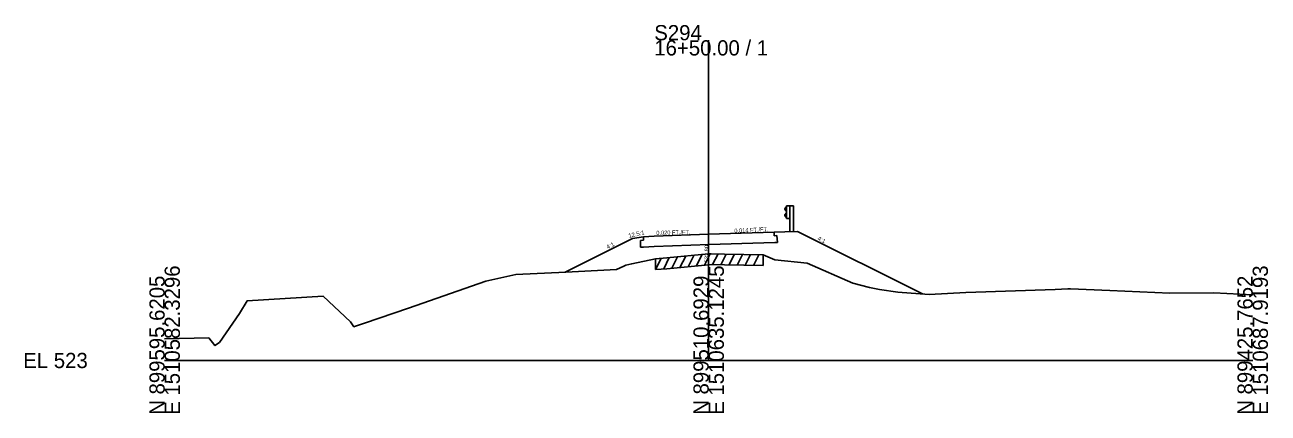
# Model space of a CAD drawing. Extents: x 974 to 2203, y -10 to 19041.
# Drawn here: x 974.3 to 1202.8, y 12990.3 to 13061.7 of the extents above; entities that cross this region are included whole.
import ezdxf

# ---------------------------------------------------------------- set-up
doc = ezdxf.new("R2010")
doc.units = 0
for name, color, linetype in [('RD_GPK_XS_Cell', 7, 'Continuous'), ('RD_XS_Base', 7, 'Continuous'), ('RD_XS_EarthShd', 7, 'Continuous'), ('RD_XS_ExGround', 7, 'Continuous'), ('RD_XS_ExPaveRet', 7, 'Continuous'), ('RD_XS_GR', 7, 'Continuous'), ('RD_XS_Pave', 7, 'Continuous'), ('RD_XS_TX_Elev_EX', 7, 'Continuous'), ('RD_XS_TX_Slope', 7, 'Continuous')]:
    doc.layers.add(name, color=color, linetype=linetype)

msp = doc.modelspace()

# ---------------------------------------------------------------- linework, layer by layer
at = {"layer": 'RD_GPK_XS_Cell'}
for p, q in [((1100, 13000), (1100, 13058.91)), ((1000, 13000), (1100, 13000)), ((1100, 13000), (1200, 13000))]:
    msp.add_line(p, q, dxfattribs=at)
at = {"layer": 'RD_XS_Base'}
for p, q in [((1088, 13022.12), (1087.5, 13022.1)), ((1087.5, 13020.83), (1087.5, 13022.1)), ((1088, 13022.12), (1088, 13022.76)), ((1112.05, 13022.96), (1112.01, 13023.59)), ((1112.05, 13022.96), (1112.55, 13022.97)), ((1112.64, 13021.7), (1112.55, 13022.97)), ((1088, 13020.85), (1087.5, 13020.83)), ((1088, 13020.85), (1090, 13020.94)), ((1090, 13020.94), (1100.07, 13021.36)), ((1110.14, 13021.63), (1100.07, 13021.36)), ((1112.14, 13021.69), (1110.14, 13021.63)), ((1112.14, 13021.69), (1112.64, 13021.7))]:
    msp.add_line(p, q, dxfattribs=at)
at = {"layer": 'RD_XS_EarthShd'}
for p, q in [((1086, 13022.43), (1073.61, 13016.23)), ((1088, 13022.76), (1086, 13022.43)), ((1112.01, 13023.59), (1114, 13023.65)), ((1114, 13023.65), (1116.32, 13023.71)), ((1116.32, 13023.71), (1139.29, 13012.23))]:
    msp.add_line(p, q, dxfattribs=at)
at = {"layer": 'RD_XS_ExGround'}
msp.add_lwpolyline([(1000, 13003.96), (1008.12, 13004.17), (1009.24, 13002.73), (1010.07, 13003.3), (1013.73, 13008.67), (1015.2, 13010.98), (1029.15, 13011.83), (1034.15, 13007.09), (1034.79, 13006.21), (1035.1, 13006.31), (1036.74, 13006.89), (1044.84, 13009.6), (1059.07, 13014.62), (1064.53, 13015.8), (1073.72, 13016.24), (1083.05, 13016.71), (1084.42, 13017.34), (1084.8, 13017.54), (1085.85, 13017.79), (1090.23, 13018.71), (1092.33, 13018.88), (1100, 13019.59), (1100.48, 13019.64), (1102.91, 13019.57), (1110.04, 13019.45), (1112.14, 13018.5), (1118.12, 13017.88), (1126.5, 13014.22), (1129.55, 13013.4), (1131.41, 13013.05), (1134.79, 13012.57), (1140.54, 13012.13), (1147.3, 13012.51), (1163.67, 13013.08), (1166.01, 13013.18), (1166.54, 13013.17), (1173.74, 13012.86), (1184.78, 13012.36), (1192.88, 13012.47), (1200, 13012.09)], dxfattribs=at)
at = {"layer": 'RD_XS_ExPaveRet'}
for p, q in [((1099.23, 13017.52), (1100.28, 13019.62)), ((1100.73, 13017.63), (1101.72, 13019.6)), ((1102.23, 13017.59), (1103.22, 13019.57)), ((1103.73, 13017.56), (1104.72, 13019.54)), ((1105.23, 13017.53), (1106.22, 13019.51)), ((1090.23, 13016.71), (1091.27, 13018.79)), ((1090.23, 13016.71), (1090.23, 13018.71)), ((1091.73, 13016.83), (1092.77, 13018.92)), ((1092.33, 13016.88), (1100, 13017.59)), ((1093.23, 13016.96), (1094.28, 13019.06)), ((1094.73, 13017.1), (1095.78, 13019.2)), ((1096.23, 13017.24), (1097.28, 13019.34)), ((1097.73, 13017.38), (1098.78, 13019.48)), ((1100, 13017.59), (1100.48, 13017.64)), ((1100.48, 13017.64), (1102.91, 13017.57)), ((1102.91, 13017.57), (1110.04, 13017.45)), ((1106.73, 13017.51), (1107.72, 13019.49)), ((1108.23, 13017.48), (1109.22, 13019.46)), ((1110.04, 13019.45), (1110.04, 13017.45)), ((1090.23, 13016.71), (1092.33, 13016.88))]:
    msp.add_line(p, q, dxfattribs=at)
at = {"layer": 'RD_XS_GR'}
for p, q in [((1114.28, 13028.31), (1114.01, 13027.91)), ((1114.01, 13027.91), (1114.01, 13027.81)), ((1114.01, 13027.81), (1114.28, 13027.41)), ((1114.01, 13026.77), (1114.28, 13027.17)), ((1114.01, 13026.67), (1114.01, 13026.77)), ((1114.28, 13026.27), (1114.01, 13026.67)), ((1114.28, 13026.12), (1114.28, 13028.45)), ((1114.28, 13028.45), (1114.94, 13028.45)), ((1114.94, 13028.45), (1114.94, 13023.67)), ((1114.94, 13028.45), (1115.61, 13028.45)), ((1115.61, 13028.45), (1115.61, 13023.69)), ((1114.28, 13026.12), (1114.94, 13026.12))]:
    msp.add_line(p, q, dxfattribs=at)
at = {"layer": 'RD_XS_Pave'}
for p, q in [((1088, 13022.76), (1090, 13022.84)), ((1090, 13022.84), (1100, 13023.26)), ((1110, 13023.54), (1100, 13023.26)), ((1112.01, 13023.59), (1110, 13023.54))]:
    msp.add_line(p, q, dxfattribs=at)

# ---------------------------------------------------------------- texts
at = {"layer": 'RD_GPK_XS_Cell'}
for s, p in [('S294', (1090, 13058.91)), ('16+50.00 / 1', (1090, 13056.11)), ('EL 523', (974, 12998.6))]:
    msp.add_text(s, height=2.8, dxfattribs=at).set_placement(p)
for s, p in [('E 1510582.3296', (1002.8, 12990)), ('E 1510635.1245', (1102.8, 12990)), ('E 1510687.9193', (1202.8, 12990)), ('N 899595.6205', (1000, 12990)), ('N 899510.6929', (1100, 12990)), ('N 899425.7652', (1200, 12990))]:
    msp.add_text(s, height=2.8, rotation=90, dxfattribs=at).set_placement(p)
at = {"layer": 'RD_XS_TX_Elev_EX'}
msp.add_text('532.80', height=0.75, rotation=90, dxfattribs=at).set_placement((1100, 13018.06))
at = {"layer": 'RD_XS_TX_Slope'}
for s, height, rotation, p in [('0.014 FT./FT.', 0.7518, 2.7727, (1104.74, 13023.48)), ('12.5:1', 0.778, 12.7511, (1085.35, 13022.56)), ('0.020 FT./FT.', 0.7518, 1.1916, (1090.38, 13023.1)), ('4:1', 0.778, 333.6312, (1119.94, 13022.21)), ('4:1', 0.778, 26.3688, (1081.44, 13020.46))]:
    msp.add_text(s, height=height, rotation=rotation, dxfattribs=at).set_placement(p)

doc.saveas('drawing.dxf')
